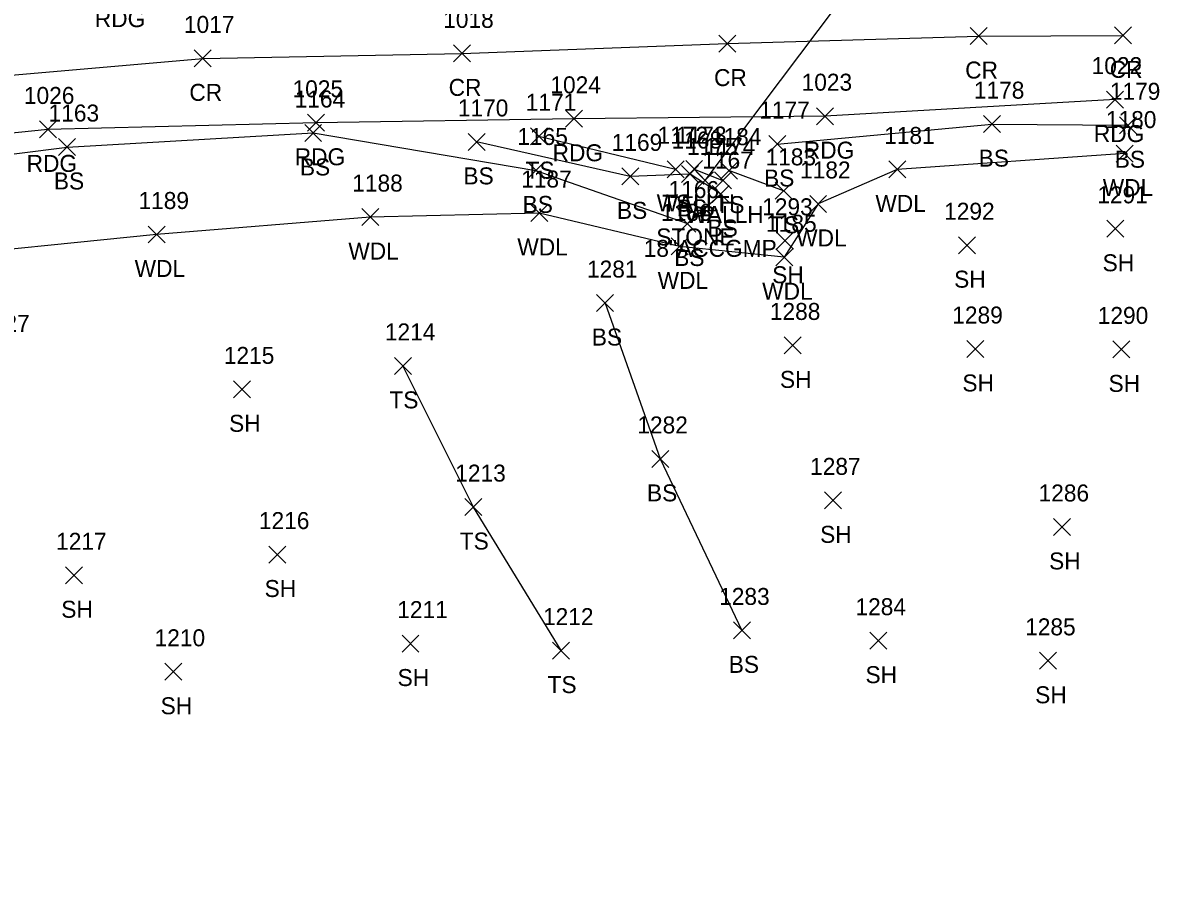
# Model space of a CAD drawing. Extents: x 1621633 to 1624015, y 417863 to 420979.
# Drawn here: x 1622191.2 to 1622325, y 418042.7 to 418146.1 of the extents above; entities that cross this region are included whole.
import ezdxf

# ---------------------------------------------------------------- set-up
doc = ezdxf.new("R2010")
doc.units = 0
for name, color, linetype in [('D_A', 7, 'Continuous'), ('D_C', 7, 'Continuous'), ('D_I', 7, 'Continuous'), ('D_TIC', 7, 'Continuous'), ('DCP', 7, 'Continuous'), ('DHW', 7, 'Continuous'), ('L_A', 7, 'Continuous'), ('L_I', 7, 'Continuous'), ('L_TIC', 7, 'Continuous'), ('LAWA', 7, 'Continuous'), ('LELB', 7, 'Continuous'), ('P_A', 7, 'Continuous'), ('P_I', 7, 'Continuous'), ('P_TIC', 7, 'Continuous'), ('PEU', 7, 'Continuous'), ('PRC', 7, 'Continuous')]:
    doc.layers.add(name, color=color, linetype=linetype)

msp = doc.modelspace()

# ---------------------------------------------------------------- linework, layer by layer
at = {"layer": 'D_TIC'}
for points in [[(1622269.26, 418127.92), (1622271.26, 418129.92)], [(1622271.26, 418127.92), (1622269.26, 418129.92)], [(1622270.54, 418126.58), (1622272.54, 418128.58)], [(1622272.54, 418126.58), (1622270.54, 418128.58)], [(1622272.64, 418126.58), (1622274.64, 418128.58)], [(1622274.64, 418126.58), (1622272.64, 418128.58)]]:
    msp.add_lwpolyline(points, dxfattribs=at)
at = {"layer": 'DCP'}
msp.add_lwpolyline([(1622271.54, 418127.58), (1622295.99, 418160.05)], dxfattribs=at)
at = {"layer": 'DHW'}
msp.add_lwpolyline([(1622270.26, 418128.92), (1622273.64, 418127.58)], dxfattribs=at)
at = {"layer": 'L_TIC'}
for points in [[(1622224.4, 418132.16), (1622226.4, 418134.16)], [(1622226.4, 418132.16), (1622224.4, 418134.16)], [(1622304.32, 418133.2), (1622306.32, 418135.2)], [(1622306.32, 418133.2), (1622304.32, 418135.2)], [(1622320.33, 418133.07), (1622322.33, 418135.07)], [(1622322.33, 418133.07), (1622320.33, 418135.07)], [(1622243.65, 418131.11), (1622245.65, 418133.11)], [(1622245.65, 418131.11), (1622243.65, 418133.11)], [(1622250.99, 418131.78), (1622252.99, 418133.78)], [(1622252.99, 418131.78), (1622250.99, 418133.78)], [(1622279.05, 418130.86), (1622281.05, 418132.86)], [(1622281.05, 418130.86), (1622279.05, 418132.86)], [(1622195.43, 418130.51), (1622197.43, 418132.51)], [(1622197.43, 418130.51), (1622195.43, 418132.51)], [(1622319.95, 418129.74), (1622321.95, 418131.74)], [(1622321.95, 418129.74), (1622319.95, 418131.74)], [(1622250.62, 418127.75), (1622252.62, 418129.75)], [(1622252.62, 418127.75), (1622250.62, 418129.75)], [(1622261.73, 418127.05), (1622263.73, 418129.05)], [(1622263.73, 418127.05), (1622261.73, 418129.05)], [(1622267.07, 418127.9), (1622269.07, 418129.9)], [(1622269.07, 418127.9), (1622267.07, 418129.9)], [(1622268.77, 418127.33), (1622270.77, 418129.33)], [(1622270.77, 418127.33), (1622268.77, 418129.33)], [(1622273.36, 418127.73), (1622275.36, 418129.73)], [(1622275.36, 418127.73), (1622273.36, 418129.73)], [(1622293.18, 418127.87), (1622295.18, 418129.87)], [(1622295.18, 418127.87), (1622293.18, 418129.87)], [(1622272.39, 418124.97), (1622274.39, 418126.97)], [(1622274.39, 418124.97), (1622272.39, 418126.97)], [(1622279.79, 418125.35), (1622281.79, 418127.35)], [(1622281.79, 418125.35), (1622279.79, 418127.35)], [(1622251.02, 418122.74), (1622253.02, 418124.74)], [(1622253.02, 418122.74), (1622251.02, 418124.74)], [(1622283.86, 418123.81), (1622285.86, 418125.81)], [(1622285.86, 418123.81), (1622283.86, 418125.81)], [(1622231.12, 418122.26), (1622233.12, 418124.26)], [(1622233.12, 418122.26), (1622231.12, 418124.26)], [(1622268.47, 418121.5), (1622270.47, 418123.5)], [(1622270.47, 418121.5), (1622268.47, 418123.5)], [(1622205.96, 418120.21), (1622207.96, 418122.21)], [(1622207.96, 418120.21), (1622205.96, 418122.21)], [(1622318.86, 418120.88), (1622320.86, 418122.88)], [(1622320.86, 418120.88), (1622318.86, 418122.88)], [(1622267.54, 418118.81), (1622269.54, 418120.81)], [(1622269.54, 418118.81), (1622267.54, 418120.81)], [(1622279.96, 418119.47), (1622281.96, 418121.47)], [(1622281.96, 418119.47), (1622279.96, 418121.47)], [(1622301.39, 418118.95), (1622303.39, 418120.95)], [(1622303.39, 418118.95), (1622301.39, 418120.95)], [(1622279.86, 418117.53), (1622281.86, 418119.53)], [(1622281.86, 418117.53), (1622279.86, 418119.53)], [(1622258.77, 418112.14), (1622260.77, 418114.14)], [(1622260.77, 418112.14), (1622258.77, 418114.14)], [(1622280.87, 418107.15), (1622282.87, 418109.15)], [(1622282.87, 418107.15), (1622280.87, 418109.15)], [(1622302.35, 418106.73), (1622304.35, 418108.73)], [(1622304.35, 418106.73), (1622302.35, 418108.73)], [(1622319.56, 418106.68), (1622321.56, 418108.68)], [(1622321.56, 418106.68), (1622319.56, 418108.68)], [(1622234.97, 418104.74), (1622236.97, 418106.74)], [(1622236.97, 418104.74), (1622234.97, 418106.74)], [(1622216.01, 418101.98), (1622218.01, 418103.98)], [(1622218.01, 418101.98), (1622216.01, 418103.98)], [(1622265.26, 418093.79), (1622267.26, 418095.79)], [(1622267.26, 418093.79), (1622265.26, 418095.79)], [(1622243.26, 418088.12), (1622245.26, 418090.12)], [(1622245.26, 418088.12), (1622243.26, 418090.12)], [(1622285.6, 418088.91), (1622287.6, 418090.91)], [(1622287.6, 418088.91), (1622285.6, 418090.91)], [(1622312.56, 418085.78), (1622314.56, 418087.78)], [(1622314.56, 418085.78), (1622312.56, 418087.78)], [(1622220.19, 418082.53), (1622222.19, 418084.53)], [(1622222.19, 418082.53), (1622220.19, 418084.53)], [(1622196.25, 418080.09), (1622198.25, 418082.09)], [(1622198.25, 418080.09), (1622196.25, 418082.09)], [(1622274.89, 418073.6), (1622276.89, 418075.6)], [(1622276.89, 418073.6), (1622274.89, 418075.6)], [(1622235.86, 418072.05), (1622237.86, 418074.05)], [(1622237.86, 418072.05), (1622235.86, 418074.05)], [(1622290.95, 418072.39), (1622292.95, 418074.39)], [(1622292.95, 418072.39), (1622290.95, 418074.39)], [(1622253.59, 418071.22), (1622255.59, 418073.22)], [(1622255.59, 418071.22), (1622253.59, 418073.22)], [(1622310.92, 418070.02), (1622312.92, 418072.02)], [(1622312.92, 418070.02), (1622310.92, 418072.02)], [(1622207.95, 418068.73), (1622209.95, 418070.73)], [(1622209.95, 418068.73), (1622207.95, 418070.73)]]:
    msp.add_lwpolyline(points, dxfattribs=at)
at = {"layer": 'LAWA'}
msp.add_lwpolyline([(1622320.95, 418130.74), (1622294.18, 418128.87), (1622284.86, 418124.81), (1622280.86, 418118.53), (1622268.54, 418119.81), (1622252.02, 418123.74), (1622232.12, 418123.26), (1622206.96, 418121.21), (1622178.23, 418118.31), (1622148.87, 418114.96), (1622127.56, 418112.54), (1622101.31, 418110.45), (1622091.62, 418108.26), (1622075.89, 418086.21), (1622049.19, 418065.74), (1622027.93, 418059.19), (1622009.75, 418042.71)], dxfattribs=at)
at = {"layer": 'LELB'}
for points in [[(1622280.05, 418131.86), (1622305.32, 418134.2), (1622321.33, 418134.07)], [(1622082.36, 418114.88), (1622069.44, 418103.95), (1622064.16, 418101.09), (1622064.96, 418098.95), (1622077.28, 418107.48), (1622086.53, 418115.98), (1622112.81, 418120.17), (1622139.27, 418124.52), (1622168, 418127.93), (1622196.43, 418131.51), (1622225.4, 418133.16), (1622251.62, 418128.75), (1622269.47, 418122.5), (1622273.39, 418125.97), (1622269.77, 418128.33), (1622262.73, 418128.05), (1622244.65, 418132.11)], [(1622251.99, 418132.78), (1622268.07, 418128.9)], [(1622280.79, 418126.35), (1622274.36, 418128.73)], [(1622259.77, 418113.14), (1622266.26, 418094.79), (1622275.89, 418074.6)], [(1622254.59, 418072.22), (1622244.26, 418089.12), (1622235.97, 418105.74)]]:
    msp.add_lwpolyline(points, dxfattribs=at)
at = {"layer": 'P_TIC'}
for points in [[(1622302.74, 418143.57), (1622304.74, 418145.57)], [(1622304.74, 418143.57), (1622302.74, 418145.57)], [(1622319.76, 418143.65), (1622321.76, 418145.65)], [(1622321.76, 418143.65), (1622319.76, 418145.65)], [(1622241.91, 418141.53), (1622243.91, 418143.53)], [(1622243.91, 418141.53), (1622241.91, 418143.53)], [(1622273.16, 418142.68), (1622275.16, 418144.68)], [(1622275.16, 418142.68), (1622273.16, 418144.68)], [(1622211.39, 418140.94), (1622213.39, 418142.94)], [(1622213.39, 418140.94), (1622211.39, 418142.94)], [(1622318.83, 418136.09), (1622320.83, 418138.09)], [(1622320.83, 418136.09), (1622318.83, 418138.09)], [(1622255.1, 418133.83), (1622257.1, 418135.83)], [(1622257.1, 418133.83), (1622255.1, 418135.83)], [(1622284.68, 418134.14), (1622286.68, 418136.14)], [(1622286.68, 418134.14), (1622284.68, 418136.14)], [(1622193.17, 418132.58), (1622195.17, 418134.58)], [(1622195.17, 418132.58), (1622193.17, 418134.58)], [(1622224.74, 418133.36), (1622226.74, 418135.36)], [(1622226.74, 418133.36), (1622224.74, 418135.36)]]:
    msp.add_lwpolyline(points, dxfattribs=at)
at = {"layer": 'PEU'}
msp.add_lwpolyline([(1622319.83, 418137.09), (1622285.68, 418135.14), (1622256.1, 418134.83), (1622225.74, 418134.36), (1622194.17, 418133.58), (1622165.78, 418130.65)], dxfattribs=at)
at = {"layer": 'PRC'}
msp.add_lwpolyline([(1621997.75, 418104.33), (1622030.17, 418110.75), (1622061.28, 418119.21), (1622091.3, 418126.36), (1622119.87, 418131.33), (1622150.17, 418136.53), (1622182.15, 418139.32), (1622212.39, 418141.94), (1622242.91, 418142.53), (1622274.16, 418143.68), (1622303.74, 418144.57), (1622320.76, 418144.65)], dxfattribs=at)

# ---------------------------------------------------------------- texts
at = {"layer": 'D_A'}
for s, p in [('WALLH', (1622265.85, 418123.92)), ('WALLH', (1622269.23, 418122.58)), ('P', (1622270.92, 418122.58))]:
    msp.add_text(s, height=2, dxfattribs=at).set_placement(p)
at = {"layer": 'D_C'}
for s, p in [('STONE', (1622265.8, 418119.92)), ('18"ACCGMP', (1622264.32, 418118.58))]:
    msp.add_text(s, height=2, dxfattribs=at).set_placement(p)
at = {"layer": 'D_I'}
for s, p in [('1173', (1622268.13, 418131.92)), ('1175', (1622269.42, 418130.58)), ('1174', (1622271.51, 418130.58))]:
    msp.add_text(s, height=2, dxfattribs=at).set_placement(p)
at = {"layer": 'L_A'}
for s, p in [('BS', (1622223.84, 418128.16)), ('BS', (1622303.76, 418129.2)), ('BS', (1622319.78, 418129.07)), ('BS', (1622243.09, 418127.11)), ('TS', (1622250.4, 418127.78)), ('BS', (1622278.49, 418126.86)), ('BS', (1622194.87, 418126.51)), ('WDL', (1622318.37, 418125.74)), ('BS', (1622250.06, 418123.75)), ('BS', (1622261.17, 418123.05)), ('TS', (1622266.48, 418123.9)), ('BS', (1622268.21, 418123.33)), ('TS', (1622272.77, 418123.73)), ('WDL', (1622291.6, 418123.87)), ('TS', (1622279.2, 418121.35)), ('BS', (1622271.83, 418120.97)), ('WDL', (1622249.44, 418118.74)), ('WDL', (1622282.27, 418119.81)), ('WDL', (1622229.54, 418118.26)), ('BS', (1622267.91, 418117.5)), ('WDL', (1622204.38, 418116.21)), ('SH', (1622318.35, 418116.88)), ('WDL', (1622265.96, 418114.81)), ('SH', (1622279.45, 418115.47)), ('SH', (1622300.87, 418114.95)), ('WDL', (1622278.27, 418113.53)), ('BS', (1622258.21, 418108.14)), ('SH', (1622280.36, 418103.15)), ('SH', (1622301.84, 418102.73)), ('SH', (1622319.05, 418102.68)), ('TS', (1622234.38, 418100.74)), ('SH', (1622215.5, 418097.98)), ('BS', (1622264.7, 418089.79)), ('TS', (1622242.66, 418084.12)), ('SH', (1622285.09, 418084.91)), ('SH', (1622312.05, 418081.78)), ('SH', (1622219.68, 418078.53)), ('SH', (1622195.74, 418076.09)), ('BS', (1622274.33, 418069.6)), ('SH', (1622235.34, 418068.05)), ('SH', (1622290.43, 418068.39)), ('TS', (1622253, 418067.22)), ('SH', (1622310.41, 418066.02)), ('SH', (1622207.44, 418064.73))]:
    msp.add_text(s, height=2, dxfattribs=at).set_placement(p)
at = {"layer": 'L_I'}
for s, p in [('1164', (1622223.22, 418136.16)), ('1178', (1622303.19, 418137.2)), ('1179', (1622319.2, 418137.07)), ('1170', (1622242.43, 418135.11)), ('1171', (1622250.43, 418135.78)), ('1177', (1622277.92, 418134.86)), ('1163', (1622194.25, 418134.51)), ('1180', (1622318.74, 418133.74)), ('1165', (1622249.44, 418131.75)), ('1169', (1622260.55, 418131.05)), ('1172', (1622265.95, 418131.9)), ('1168', (1622267.6, 418131.33)), ('1184', (1622272.23, 418131.73)), ('1181', (1622292.63, 418131.87)), ('1167', (1622271.22, 418128.97)), ('1183', (1622278.66, 418129.35)), ('1187', (1622249.89, 418126.74)), ('1182', (1622282.73, 418127.81)), ('1188', (1622230, 418126.26)), ('1166', (1622267.24, 418125.5)), ('1189', (1622204.83, 418124.21)), ('1291', (1622317.73, 418124.88)), ('1186', (1622266.36, 418122.81)), ('1293', (1622278.27, 418123.47)), ('1292', (1622299.69, 418122.95)), ('1185', (1622278.73, 418121.53)), ('1281', (1622257.64, 418116.14)), ('1288', (1622279.17, 418111.15)), ('1289', (1622300.65, 418110.73)), ('1290', (1622317.78, 418110.68)), ('1227', (1622186.07, 418109.74)), ('1214', (1622233.84, 418108.74)), ('1215', (1622214.88, 418105.98)), ('1282', (1622263.57, 418097.79)), ('1213', (1622242.13, 418092.12)), ('1287', (1622283.91, 418092.91)), ('1286', (1622310.81, 418089.78)), ('1216', (1622219.01, 418086.53)), ('1217', (1622195.13, 418084.09)), ('1283', (1622273.2, 418077.6)), ('1211', (1622235.3, 418076.05)), ('1284', (1622289.25, 418076.39)), ('1212', (1622252.46, 418075.22)), ('1285', (1622309.23, 418074.02)), ('1210', (1622206.73, 418072.73))]:
    msp.add_text(s, height=2, dxfattribs=at).set_placement(p)
at = {"layer": 'P_A'}
for s, p in [('RDG', (1622199.69, 418145.62)), ('CR', (1622302.17, 418139.57)), ('CR', (1622319.19, 418139.65)), ('CR', (1622241.35, 418137.53)), ('CR', (1622272.6, 418138.68)), ('CR', (1622210.82, 418136.94)), ('RDG', (1622317.32, 418132.09)), ('RDG', (1622253.59, 418129.83)), ('RDG', (1622283.17, 418130.14)), ('RDG', (1622191.66, 418128.58)), ('RDG', (1622223.23, 418129.36))]:
    msp.add_text(s, height=2, dxfattribs=at).set_placement(p)
at = {"layer": 'P_I'}
for s, p in [('1018', (1622240.71, 418145.53)), ('1017', (1622210.18, 418144.94)), ('1022', (1622317.06, 418140.09)), ('1024', (1622253.33, 418137.83)), ('1023', (1622282.91, 418138.14)), ('1026', (1622191.34, 418136.58)), ('1025', (1622222.97, 418137.36))]:
    msp.add_text(s, height=2, dxfattribs=at).set_placement(p)

doc.saveas('drawing.dxf')
